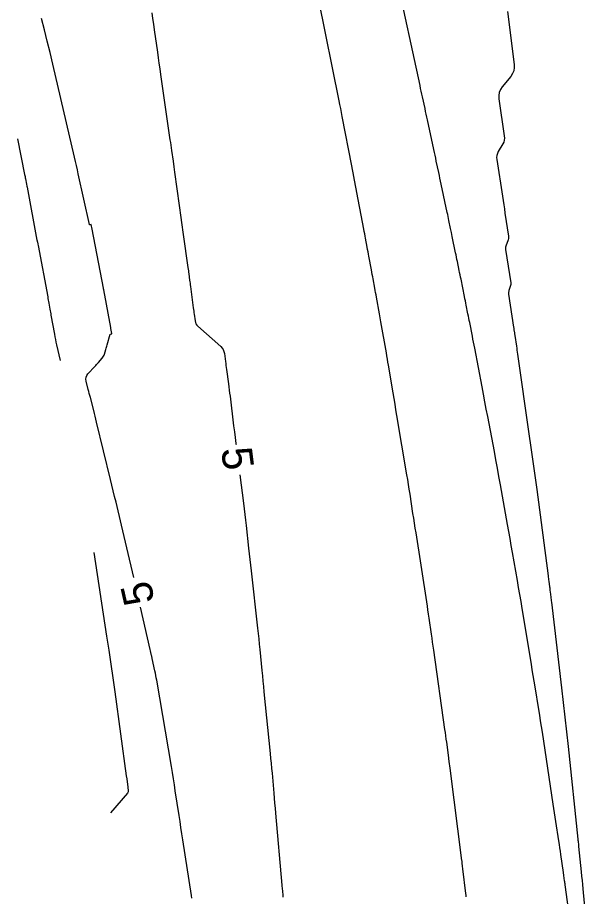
# Model space of a CAD drawing. Extents: x 1797419 to 1809236, y 248759 to 251512.
# Drawn here: x 1799089.4 to 1799201.6, y 251120.8 to 251292.8 of the extents above; entities that cross this region are included whole.
import ezdxf

# ---------------------------------------------------------------- set-up
doc = ezdxf.new("R2010")
doc.units = 0
doc.layers.add('33', color=7, linetype='Continuous')
doc.layers.add('34', color=7, linetype='Continuous')

msp = doc.modelspace()

# ---------------------------------------------------------------- linework, layer by layer
at = {"layer": '33'}
for points in [[(1799115.68, 251293.75), (1799115.84, 251292.65), (1799116, 251291.55), (1799116.16, 251290.46), (1799116.79, 251286.08), (1799116.94, 251284.98), (1799117.1, 251283.89), (1799117.26, 251282.79), (1799117.42, 251281.7), (1799119.25, 251268.89), (1799119.33, 251268.37), (1799119.4, 251267.84), (1799119.48, 251267.32), (1799119.55, 251266.8), (1799119.85, 251264.7), (1799120, 251263.65), (1799120.15, 251262.6), (1799121.07, 251256.08), (1799121.14, 251255.6), (1799121.2, 251255.13), (1799121.27, 251254.65), (1799121.33, 251254.17), (1799121.6, 251252.26), (1799121.66, 251251.79), (1799121.73, 251251.31), (1799121.79, 251250.83), (1799121.86, 251250.36), (1799122.76, 251243.9), (1799122.81, 251243.59), (1799122.85, 251243.29), (1799122.89, 251242.98), (1799122.93, 251242.67), (1799123.1, 251241.45), (1799123.14, 251241.14), (1799123.18, 251240.83), (1799123.22, 251240.53), (1799123.26, 251240.22), (1799123.82, 251236.04), (1799123.86, 251235.72), (1799123.9, 251235.4), (1799123.94, 251235.08), (1799123.99, 251234.76), (1799124.16, 251233.48), (1799124.22, 251233.18), (1799124.34, 251232.9), (1799124.51, 251232.64), (1799124.72, 251232.42), (1799129.21, 251228.44), (1799129.47, 251228.16), (1799129.68, 251227.85), (1799129.82, 251227.5), (1799129.91, 251227.12), (1799130.12, 251225.55), (1799130.17, 251225.15), (1799130.22, 251224.76), (1799130.27, 251224.36), (1799130.33, 251223.97), (1799130.7, 251221.15), (1799130.78, 251220.55), (1799130.85, 251219.94), (1799130.93, 251219.34), (1799131.01, 251218.74), (1799131.72, 251212.95), (1799131.87, 251211.78), (1799132.01, 251210.62), (1799132.16, 251209.45), (1799132.18, 251209.29)], [(1799112.15, 251183.27), (1799110.83, 251189.05), (1799110.57, 251190.17), (1799110.31, 251191.28), (1799110.04, 251192.4), (1799109.77, 251193.51), (1799108.69, 251197.97), (1799108.42, 251199.08), (1799108.15, 251200.2), (1799107.88, 251201.31), (1799107.61, 251202.43), (1799104.88, 251213.68), (1799104.74, 251214.24), (1799104.6, 251214.8), (1799104.46, 251215.36), (1799104.32, 251215.92), (1799103.67, 251218.47), (1799103.57, 251218.87), (1799103.46, 251219.27), (1799103.36, 251219.67), (1799103.26, 251220.07), (1799102.85, 251221.67), (1799102.79, 251222.06), (1799102.83, 251222.43), (1799102.97, 251222.77), (1799103.2, 251223.08), (1799104.55, 251224.57), (1799104.72, 251224.77), (1799104.9, 251224.96), (1799105.08, 251225.16), (1799105.25, 251225.35), (1799106, 251226.18), (1799106.14, 251226.36), (1799106.26, 251226.55), (1799106.36, 251226.76), (1799106.44, 251226.98), (1799106.7, 251227.88), (1799106.76, 251228.1), (1799106.83, 251228.33), (1799106.89, 251228.55), (1799106.96, 251228.78), (1799107.55, 251230.86), (1799107.55, 251230.87), (1799107.56, 251230.87), (1799107.56, 251230.87), (1799107.57, 251230.88), (1799107.61, 251230.88), (1799107.81, 251230.92), (1799107.84, 251230.94), (1799107.86, 251230.95), (1799107.87, 251230.98), (1799107.87, 251231.01), (1799107.69, 251232), (1799107.69, 251232.04), (1799107.68, 251232.08), (1799107.67, 251232.11), (1799107.67, 251232.15), (1799106.29, 251239.54), (1799106.25, 251239.76), (1799106.25, 251239.79), (1799106.24, 251239.81), (1799106.24, 251239.84), (1799106.23, 251239.87), (1799104.02, 251251.42), (1799104.02, 251251.43), (1799103.85, 251252.32), (1799103.85, 251252.32), (1799103.84, 251252.32), (1799103.84, 251252.32), (1799103.84, 251252.32), (1799103.6, 251252.27), (1799103.56, 251252.27), (1799103.54, 251252.28), (1799103.52, 251252.3), (1799103.51, 251252.33), (1799101.31, 251262.25), (1799101.13, 251263.06), (1799100.95, 251263.87), (1799100.77, 251264.68), (1799100.58, 251265.49), (1799096.31, 251283.74), (1799095.78, 251285.98), (1799095.24, 251288.21), (1799094.68, 251290.44), (1799094.13, 251292.64)], [(1799089.42, 251269.08), (1799090.8, 251262.11), (1799090.84, 251261.9), (1799090.88, 251261.7), (1799090.92, 251261.49), (1799090.95, 251261.29), (1799091.15, 251260.26), (1799091.23, 251259.85), (1799091.27, 251259.64), (1799093.22, 251249.29), (1799093.24, 251249.2), (1799093.26, 251249.11), (1799093.27, 251249.02), (1799093.29, 251248.92), (1799093.37, 251248.47), (1799093.43, 251248.2), (1799095.31, 251238.15), (1799095.37, 251237.85), (1799095.42, 251237.55), (1799095.48, 251237.26), (1799095.53, 251236.96), (1799095.75, 251235.77), (1799095.8, 251235.47), (1799095.85, 251235.17), (1799095.91, 251234.87), (1799095.96, 251234.58), (1799096.63, 251230.9), (1799096.73, 251230.38), (1799096.83, 251229.85), (1799096.94, 251229.33), (1799097.06, 251228.81), (1799097.76, 251225.69)], [(1799132.93, 251203.33), (1799133.62, 251197.81), (1799133.76, 251196.7), (1799133.89, 251195.6), (1799134.02, 251194.5), (1799134.15, 251193.4), (1799134.64, 251188.99), (1799134.77, 251187.89), (1799134.89, 251186.79), (1799135.02, 251185.68), (1799135.14, 251184.58), (1799136.41, 251173.32), (1799136.52, 251172.29), (1799136.63, 251171.25), (1799136.74, 251170.21), (1799136.85, 251169.17), (1799137.25, 251165.02), (1799137.36, 251163.98), (1799137.46, 251162.94), (1799137.56, 251161.91), (1799137.66, 251160.87), (1799138.87, 251148.83), (1799138.96, 251147.85), (1799139.05, 251146.88), (1799139.14, 251145.9), (1799139.23, 251144.93), (1799139.57, 251141.03), (1799139.65, 251140.06), (1799139.74, 251139.08), (1799139.82, 251138.11), (1799139.91, 251137.13), (1799141.16, 251123.02), (1799141.18, 251122.76), (1799141.21, 251122.5), (1799141.23, 251122.25), (1799141.25, 251121.99), (1799141.33, 251120.97), (1799141.35, 251120.71)], [(1799104.38, 251188.14), (1799106.86, 251171.77), (1799107.26, 251169.05), (1799107.66, 251166.32), (1799108.06, 251163.59), (1799108.44, 251160.86), (1799110.71, 251144.44), (1799110.8, 251143.84), (1799110.95, 251142.76), (1799110.97, 251142.61), (1799110.99, 251142.46), (1799111, 251142.31), (1799111.02, 251142.16), (1799111.1, 251141.57), (1799111.1, 251141.43), (1799111.08, 251141.29), (1799111.02, 251141.17), (1799110.94, 251141.05), (1799107.64, 251137.21)], [(1799123.55, 251120.5), (1799123.47, 251121.03), (1799121.78, 251131.91), (1799121.6, 251133.11), (1799121.41, 251134.3), (1799121.23, 251135.5), (1799121.04, 251136.69), (1799120.3, 251141.48), (1799120.11, 251142.67), (1799119.92, 251143.87), (1799119.72, 251145.06), (1799119.52, 251146.25), (1799116.66, 251163.13), (1799116.58, 251163.59), (1799116.5, 251164.05), (1799116.41, 251164.5), (1799116.31, 251164.96), (1799115.79, 251167.39), (1799115.76, 251167.54), (1799115.72, 251167.69), (1799115.69, 251167.84), (1799115.65, 251167.99), (1799115.52, 251168.58), (1799115.45, 251168.88), (1799115.38, 251169.18), (1799113.49, 251177.42)]]:
    msp.add_lwpolyline(points, dxfattribs=at)
at = {"layer": '34'}
for points in [[(1799198.46, 251109.7), (1799196.63, 251123.09), (1799196.6, 251123.3), (1799196.57, 251123.5), (1799196.54, 251123.71), (1799196.51, 251123.91), (1799196.37, 251124.93), (1799196.28, 251125.54), (1799195.77, 251129.06), (1799195.68, 251129.71), (1799195.58, 251130.37), (1799195.49, 251131.02), (1799195.39, 251131.68), (1799194.81, 251135.49), (1799194.68, 251136.35), (1799194.55, 251137.2), (1799194.42, 251138.06), (1799194.29, 251138.91), (1799192.16, 251152.95), (1799191.99, 251154.07), (1799191.82, 251155.18), (1799191.64, 251156.3), (1799191.46, 251157.41), (1799190.73, 251161.86), (1799190.55, 251162.97), (1799190.36, 251164.08), (1799190.18, 251165.19), (1799190, 251166.31), (1799188.21, 251177.21), (1799187.98, 251178.58), (1799187.75, 251179.95), (1799187.51, 251181.32), (1799187.27, 251182.68), (1799186.3, 251188.15), (1799186.06, 251189.52), (1799185.82, 251190.89), (1799185.58, 251192.25), (1799185.33, 251193.62), (1799183.95, 251201.41), (1799183.66, 251203.04), (1799183.37, 251204.66), (1799183.07, 251206.29), (1799182.76, 251207.91), (1799181.46, 251214.75), (1799181.18, 251216.2), (1799180.91, 251217.66), (1799180.63, 251219.12), (1799180.35, 251220.58), (1799178.91, 251228.15), (1799178.8, 251228.74), (1799178.69, 251229.32), (1799178.57, 251229.9), (1799178.46, 251230.49), (1799177.93, 251233.13), (1799177.85, 251233.55), (1799177.76, 251233.98), (1799177.68, 251234.41), (1799177.59, 251234.83), (1799177.26, 251236.53), (1799177.17, 251236.96), (1799177.09, 251237.38), (1799177, 251237.81), (1799176.91, 251238.23), (1799176.23, 251241.62), (1799176.14, 251242.05), (1799176.05, 251242.48), (1799175.96, 251242.92), (1799175.88, 251243.35), (1799175.53, 251245.07), (1799175.44, 251245.5), (1799175.35, 251245.94), (1799175.26, 251246.37), (1799175.17, 251246.8), (1799174.51, 251250.01), (1799174.35, 251250.79), (1799174.18, 251251.57), (1799173.86, 251253.14), (1799173.78, 251253.53), (1799173.7, 251253.92), (1799173.62, 251254.31), (1799173.53, 251254.7), (1799172.35, 251260.25), (1799172.23, 251260.81), (1799172.11, 251261.38), (1799171.99, 251261.94), (1799171.87, 251262.5), (1799171.39, 251264.76), (1799171.27, 251265.32), (1799171.15, 251265.89), (1799171.03, 251266.45), (1799170.91, 251267.01), (1799169.66, 251272.8), (1799169.54, 251273.36), (1799169.42, 251273.92), (1799169.3, 251274.48), (1799169.18, 251275.04), (1799168.7, 251277.29), (1799168.58, 251277.85), (1799168.45, 251278.41), (1799168.33, 251278.97), (1799168.21, 251279.53), (1799163.62, 251300.85)], [(1799177.27, 251120.78), (1799177.23, 251121.09), (1799177.2, 251121.41), (1799176.61, 251126.24), (1799176.55, 251126.78), (1799176.48, 251127.33), (1799176.46, 251127.46), (1799176.45, 251127.6), (1799176.43, 251127.74), (1799176.41, 251127.87), (1799174.08, 251145.94), (1799173.92, 251147.21), (1799173.75, 251148.47), (1799173.43, 251151), (1799173.34, 251151.63), (1799173.26, 251152.26), (1799173.17, 251152.89), (1799173.09, 251153.52), (1799170.89, 251169), (1799170.77, 251169.79), (1799170.66, 251170.58), (1799170.55, 251171.37), (1799170.44, 251172.16), (1799169.99, 251175.31), (1799169.88, 251176.1), (1799169.76, 251176.89), (1799169.64, 251177.67), (1799169.52, 251178.46), (1799167.42, 251191.99), (1799167.28, 251192.93), (1799167.13, 251193.88), (1799166.98, 251194.83), (1799166.83, 251195.78), (1799166.25, 251199.58), (1799166.1, 251200.52), (1799165.95, 251201.47), (1799165.79, 251202.42), (1799165.63, 251203.37), (1799163.68, 251214.95), (1799163.5, 251216.06), (1799163.31, 251217.17), (1799163.13, 251218.27), (1799162.94, 251219.38), (1799162.03, 251224.79), (1799161.93, 251225.4), (1799161.82, 251226.01), (1799161.71, 251226.63), (1799161.61, 251227.24), (1799160.54, 251233.26), (1799160.47, 251233.65), (1799160.4, 251234.04), (1799160.33, 251234.43), (1799160.26, 251234.83), (1799159.67, 251238.11), (1799159.59, 251238.56), (1799159.5, 251239), (1799159.42, 251239.45), (1799159.34, 251239.89), (1799159.02, 251241.67), (1799158.94, 251242.11), (1799158.86, 251242.56), (1799158.78, 251243), (1799158.69, 251243.45), (1799158.2, 251246.12), (1799158.12, 251246.55), (1799158.04, 251246.99), (1799157.95, 251247.43), (1799157.87, 251247.87), (1799157.55, 251249.63), (1799157.46, 251250.07), (1799157.38, 251250.51), (1799157.3, 251250.95), (1799157.22, 251251.39), (1799156.43, 251255.5), (1799156.3, 251256.19), (1799156.16, 251256.89), (1799156.03, 251257.58), (1799155.9, 251258.27), (1799155.37, 251261.04), (1799155.24, 251261.74), (1799155.11, 251262.43), (1799154.97, 251263.12), (1799154.84, 251263.82), (1799152.99, 251273.47), (1799152.84, 251274.24), (1799152.69, 251275.01), (1799152.53, 251275.79), (1799152.38, 251276.56), (1799148.41, 251296.25)], [(1799185.36, 251294.02), (1799186.63, 251283.68), (1799186.65, 251283.04), (1799186.55, 251282.43), (1799186.32, 251281.86), (1799185.96, 251281.33), (1799184.29, 251279.26), (1799183.93, 251278.73), (1799183.71, 251278.16), (1799183.61, 251277.55), (1799183.64, 251276.91), (1799184.71, 251269.68), (1799184.74, 251269.26), (1799184.7, 251268.86), (1799184.59, 251268.48), (1799184.4, 251268.1), (1799183.53, 251266.63), (1799183.35, 251266.26), (1799183.24, 251265.87), (1799183.2, 251265.47), (1799183.23, 251265.06), (1799184.34, 251257.85), (1799184.47, 251257.02), (1799184.6, 251256.2), (1799184.72, 251255.37), (1799184.84, 251254.54), (1799185.51, 251250.02), (1799185.53, 251249.79), (1799185.52, 251249.58), (1799185.48, 251249.36), (1799185.41, 251249.15), (1799185.06, 251248.31), (1799184.99, 251248.1), (1799184.95, 251247.88), (1799184.94, 251247.67), (1799184.96, 251247.44), (1799185.96, 251240.95), (1799185.98, 251240.75), (1799185.97, 251240.56), (1799185.94, 251240.37), (1799185.88, 251240.18), (1799185.62, 251239.44), (1799185.57, 251239.25), (1799185.54, 251239.06), (1799185.53, 251238.87), (1799185.55, 251238.68), (1799186.52, 251232.23), (1799186.54, 251232.1), (1799186.56, 251231.96), (1799186.58, 251231.83), (1799186.6, 251231.7), (1799186.68, 251231.16), (1799186.71, 251231.03), (1799186.73, 251230.9), (1799186.74, 251230.76), (1799186.76, 251230.63), (1799187.07, 251228.52), (1799187.13, 251228.13), (1799187.18, 251227.73), (1799187.24, 251227.34), (1799187.3, 251226.94), (1799189.53, 251211.38), (1799189.92, 251208.66), (1799190.3, 251205.93), (1799190.67, 251203.2), (1799191.04, 251200.48), (1799193.27, 251183.59), (1799193.31, 251183.32), (1799193.34, 251183.06), (1799193.38, 251182.79), (1799193.41, 251182.53), (1799193.55, 251181.45), (1799193.59, 251181.2), (1799193.62, 251180.95), (1799193.65, 251180.7), (1799193.68, 251180.44), (1799193.8, 251179.43), (1799193.83, 251179.18), (1799193.86, 251178.93), (1799193.89, 251178.68), (1799193.92, 251178.42), (1799195.9, 251161.68), (1799196.24, 251158.81), (1799196.56, 251155.93), (1799196.88, 251153.05), (1799197.19, 251150.17), (1799199.11, 251132.01), (1799199.12, 251131.9), (1799199.13, 251131.79), (1799199.15, 251131.68), (1799199.16, 251131.57), (1799199.22, 251130.95), (1799199.23, 251130.92), (1799199.23, 251130.89), (1799199.23, 251130.86), (1799199.24, 251130.83), (1799199.25, 251130.68), (1799199.26, 251130.59), (1799199.76, 251125.65), (1799199.84, 251124.81), (1799199.92, 251123.98), (1799200, 251123.14), (1799200.08, 251122.3), (1799201.56, 251106.11)]]:
    msp.add_lwpolyline(points, dxfattribs=at)

# ---------------------------------------------------------------- texts
at = {"layer": '33'}
for rotation, p in [(277.1564, (1799129.27, 251208.41)), (102.9092, (1799116.3, 251178.59))]:
    msp.add_text('5', height=6, rotation=rotation, dxfattribs=at).set_placement(p)

doc.saveas('drawing.dxf')
